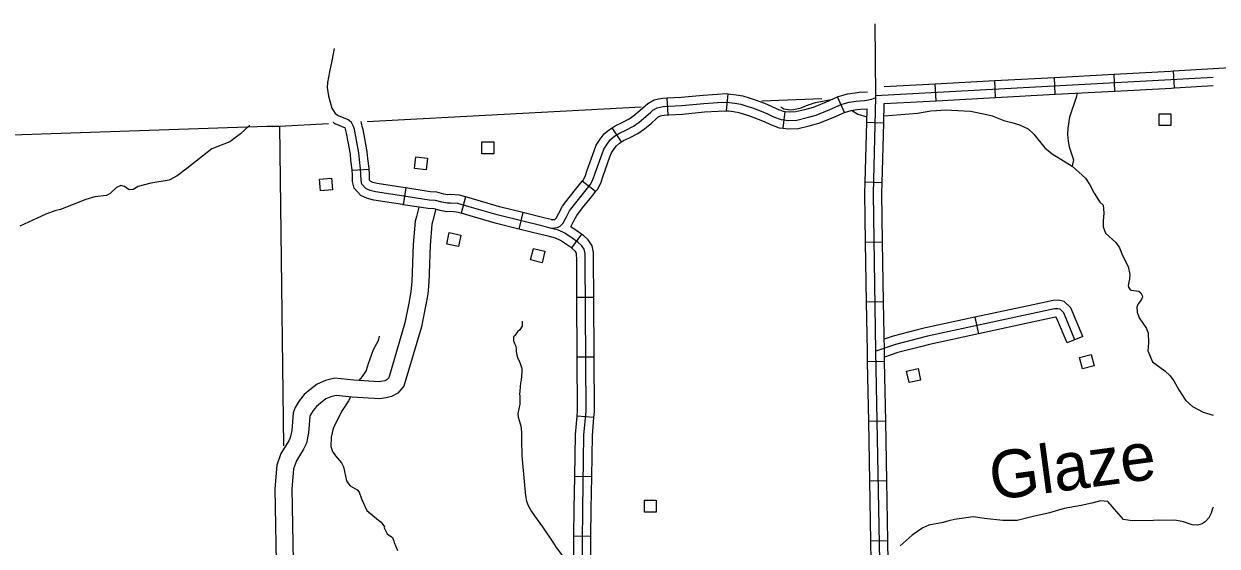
# Model space of a CAD drawing. Extents: x 1369885 to 1370219, y 379980 to 380218.
# Drawn here: x 1370079.7 to 1370121.66, y 380108.07 to 380126.43 of the extents above; entities that cross this region are included whole.
import ezdxf

# ---------------------------------------------------------------- set-up
doc = ezdxf.new("R2010")
doc.units = 0
for name, color, linetype in [('Level 1', 7, 'Continuous'), ('Level 30', 7, 'Continuous'), ('Level 32', 7, 'Continuous'), ('Level 35', 7, 'Continuous'), ('Level 45', 7, 'Continuous'), ('Level 46', 7, 'Continuous'), ('Level 5', 7, 'Continuous'), ('Level 56', 7, 'Continuous')]:
    doc.layers.add(name, color=color, linetype=linetype)

msp = doc.modelspace()

# ---------------------------------------------------------------- linework, layer by layer
at = {"layer": 'Level 1'}
for points in [[(1370091.768, 380123.003), (1370101.408, 380123.518)], [(1370105.652, 380123.724), (1370107.758, 380123.802)], [(1370068.595, 380122.2), (1370071.687, 380122.275), (1370088.242, 380122.837), (1370088.683, 380122.838), (1370090.411, 380122.931)]]:
    msp.add_lwpolyline(points, dxfattribs=at)
at = {"layer": 'Level 30'}
msp.add_lwpolyline([(1370121.526, 380124.859), (1370128.518, 380125.268)], dxfattribs=at)
at = {"layer": 'Level 32'}
for p, q in [((1370120.169, 380124.182), (1370120.135, 380124.777)), ((1370111.779, 380123.728), (1370111.747, 380124.324)), ((1370113.876, 380123.841), (1370113.844, 380124.437)), ((1370115.974, 380123.955), (1370115.942, 380124.55)), ((1370118.071, 380124.068), (1370118.039, 380124.664)), ((1370104.413, 380123.376), (1370104.465, 380123.97)), ((1370108.556, 380123.317), (1370108.313, 380123.862)), ((1370102.362, 380123.232), (1370102.327, 380123.828)), ((1370106.397, 380122.76), (1370106.469, 380123.352)), ((1370100.714, 380122.279), (1370100.383, 380122.775)), ((1370109.94, 380122.944), (1370109.343, 380122.96)), ((1370091.84, 380121.31), (1370091.244, 380121.275)), ((1370099.808, 380120.533), (1370099.336, 380120.898)), ((1370093.13, 380120.662), (1370093.037, 380120.073)), ((1370109.886, 380120.845), (1370109.289, 380120.86)), ((1370095.234, 380120.344), (1370095.073, 380119.77)), ((1370097.252, 380119.795), (1370097.108, 380119.216)), ((1370099.307, 380119.034), (1370098.953, 380118.554)), ((1370109.9, 380118.757), (1370109.303, 380118.747)), ((1370099.745, 380116.813), (1370099.148, 380116.81)), ((1370109.935, 380116.657), (1370109.338, 380116.647)), ((1370099.757, 380114.713), (1370099.16, 380114.709)), ((1370109.97, 380114.558), (1370109.373, 380114.547)), ((1370099.749, 380112.585), (1370099.155, 380112.638)), ((1370110.009, 380112.458), (1370109.412, 380112.447)), ((1370099.671, 380110.509), (1370099.074, 380110.519)), ((1370110.047, 380110.358), (1370109.451, 380110.347)), ((1370099.643, 380108.411), (1370099.046, 380108.417)), ((1370110.086, 380108.258), (1370109.489, 380108.247))]:
    msp.add_line(p, q, dxfattribs=at)
for points in [[(1370109.666, 380123.913), (1370109.633, 380126.43)], [(1370090.608, 380125.566), (1370090.525, 380125.13), (1370090.448, 380124.744), (1370090.376, 380124.374), (1370090.36, 380124.187), (1370090.409, 380123.883), (1370090.531, 380123.465), (1370090.652, 380123.276), (1370090.773, 380123.194), (1370091.099, 380123.062), (1370091.214, 380122.984)], [(1370118.039, 380124.664), (1370120.023, 380124.771), (1370120.135, 380124.777)], [(1370120.135, 380124.777), (1370121.526, 380124.859)], [(1370109.666, 380123.913), (1370120.04, 380124.473), (1370121.526, 380124.56)], [(1370109.96, 380124.228), (1370111.747, 380124.324)], [(1370111.747, 380124.324), (1370113.844, 380124.437)], [(1370113.844, 380124.437), (1370115.942, 380124.55)], [(1370115.942, 380124.55), (1370118.039, 380124.664)], [(1370120.169, 380124.182), (1370121.526, 380124.261)], [(1370102.327, 380123.828), (1370102.352, 380123.829), (1370102.82, 380123.854), (1370103.59, 380123.928), (1370104.087, 380123.959), (1370104.396, 380123.976), (1370104.465, 380123.97)], [(1370104.465, 380123.97), (1370104.549, 380123.963), (1370104.748, 380123.939), (1370104.98, 380123.896), (1370105.211, 380123.827), (1370105.418, 380123.758), (1370105.745, 380123.637), (1370105.982, 380123.535), (1370106.182, 380123.437), (1370106.403, 380123.36), (1370106.469, 380123.352)], [(1370106.469, 380123.352), (1370106.619, 380123.334), (1370106.843, 380123.343), (1370107.168, 380123.424), (1370107.467, 380123.501), (1370107.928, 380123.691), (1370108.313, 380123.862)], [(1370106.886, 380123.046), (1370107.242, 380123.135), (1370107.561, 380123.218), (1370108.045, 380123.416), (1370108.442, 380123.593), (1370108.595, 380123.639), (1370108.728, 380123.68), (1370108.968, 380123.712), (1370109.106, 380123.728), (1370109.268, 380123.74), (1370109.343, 380123.752), (1370109.515, 380123.778), (1370109.585, 380123.81), (1370109.664, 380123.843)], [(1370108.313, 380123.862), (1370108.338, 380123.873), (1370108.508, 380123.924), (1370108.664, 380123.973), (1370108.931, 380124.008), (1370109.078, 380124.025), (1370109.366, 380124.046)], [(1370110.686, 380062.06), (1370110.698, 380062.13), (1370110.711, 380062.232), (1370110.72, 380062.336), (1370110.739, 380064.517), (1370110.44, 380079.332), (1370110.285, 380083.111), (1370110.263, 380085.837), (1370110.134, 380092.024), (1370109.791, 380107.409), (1370109.801, 380107.535), (1370109.665, 380114.927), (1370109.587, 380119.631), (1370109.578, 380120.463), (1370109.664, 380123.843), (1370109.666, 380123.913)], [(1370111.779, 380123.728), (1370113.876, 380123.841)], [(1370113.876, 380123.841), (1370115.974, 380123.955)], [(1370115.974, 380123.955), (1370118.071, 380124.068)], [(1370118.071, 380124.068), (1370120.057, 380124.175), (1370120.169, 380124.182)], [(1370098.207, 380119.249), (1370098.369, 380119.255), (1370098.466, 380119.269), (1370098.56, 380119.318), (1370098.656, 380119.409), (1370098.78, 380119.641), (1370098.89, 380119.856), (1370099.108, 380120.143), (1370099.381, 380120.48), (1370099.522, 380120.651), (1370099.615, 380120.772), (1370099.712, 380120.952), (1370099.787, 380121.185), (1370100.032, 380121.864), (1370100.097, 380122.025), (1370100.208, 380122.205), (1370100.321, 380122.354), (1370100.476, 380122.479), (1370100.641, 380122.589), (1370100.87, 380122.694), (1370101.139, 380122.834), (1370101.338, 380122.972), (1370101.572, 380123.17), (1370101.743, 380123.321), (1370101.821, 380123.391), (1370101.977, 380123.482)], [(1370100.383, 380122.775), (1370100.495, 380122.85), (1370100.739, 380122.962), (1370100.985, 380123.09), (1370101.156, 380123.209), (1370101.377, 380123.396), (1370101.544, 380123.543), (1370101.644, 380123.634), (1370101.868, 380123.763), (1370102.022, 380123.797), (1370102.153, 380123.817), (1370102.327, 380123.828)], [(1370101.977, 380123.482), (1370102.077, 380123.504), (1370102.184, 380123.52), (1370102.369, 380123.531), (1370102.842, 380123.556), (1370103.614, 380123.631), (1370104.104, 380123.661), (1370104.391, 380123.677), (1370104.518, 380123.666), (1370104.703, 380123.644), (1370104.909, 380123.606)], [(1370104.909, 380123.606), (1370105.121, 380123.542), (1370105.319, 380123.476), (1370105.634, 380123.36), (1370105.857, 380123.264), (1370106.067, 380123.161), (1370106.335, 380123.068), (1370106.607, 380123.035), (1370106.886, 380123.046)], [(1370108.547, 380123.313), (1370108.682, 380123.354), (1370108.792, 380123.388), (1370109.004, 380123.416), (1370109.134, 380123.43), (1370109.356, 380123.447)], [(1370109.343, 380122.96), (1370109.356, 380123.447)], [(1370109.94, 380122.944), (1370109.957, 380123.63)], [(1370109.957, 380123.63), (1370111.779, 380123.728)], [(1370100.714, 380122.279), (1370100.787, 380122.328), (1370101.001, 380122.426), (1370101.294, 380122.578), (1370101.52, 380122.735), (1370101.767, 380122.944), (1370101.942, 380123.099), (1370101.997, 380123.149), (1370102.087, 380123.2), (1370102.132, 380123.21), (1370102.216, 380123.223), (1370102.362, 380123.232)], [(1370102.362, 380123.232), (1370102.386, 380123.233), (1370102.864, 380123.258), (1370103.637, 380123.333), (1370104.122, 380123.363), (1370104.387, 380123.378), (1370104.413, 380123.376)], [(1370104.413, 380123.376), (1370104.487, 380123.37), (1370104.658, 380123.349), (1370104.839, 380123.315), (1370105.031, 380123.258), (1370105.221, 380123.194), (1370105.523, 380123.083), (1370105.732, 380122.992), (1370105.952, 380122.886), (1370106.267, 380122.775), (1370106.397, 380122.76)], [(1370106.397, 380122.76), (1370106.595, 380122.736), (1370106.929, 380122.749), (1370107.315, 380122.846), (1370107.656, 380122.934), (1370108.163, 380123.142), (1370108.556, 380123.317)], [(1370090.574, 380122.969), (1370090.632, 380122.93), (1370091.001, 380122.779)], [(1370091.244, 380121.275), (1370091.242, 380121.301), (1370091.201, 380121.632), (1370091.183, 380121.853), (1370091.101, 380122.288), (1370091.05, 380122.589), (1370091.036, 380122.639), (1370091.001, 380122.779)], [(1370099.331, 380107.04), (1370099.354, 380109.38), (1370099.396, 380111.973), (1370099.47, 380112.808), (1370099.438, 380118.145), (1370099.436, 380118.356), (1370099.408, 380118.507), (1370099.318, 380118.631), (1370099.185, 380118.753), (1370098.987, 380118.899), (1370098.719, 380119.07), (1370098.504, 380119.178), (1370098.207, 380119.249), (1370097.956, 380119.313), (1370096.348, 380119.713), (1370095.278, 380120.022), (1370094.964, 380120.11), (1370094.705, 380120.127), (1370094.594, 380120.121), (1370094.403, 380120.156), (1370094.177, 380120.217), (1370093.949, 380120.232), (1370093.063, 380120.371), (1370092.069, 380120.528), (1370091.876, 380120.574), (1370091.722, 380120.645), (1370091.584, 380120.791), (1370091.556, 380120.927), (1370091.551, 380121.142), (1370091.54, 380121.328), (1370091.498, 380121.663), (1370091.479, 380121.893), (1370091.394, 380122.341), (1370091.341, 380122.653), (1370091.325, 380122.714), (1370091.297, 380122.824), (1370091.214, 380122.984)], [(1370091.84, 380121.31), (1370091.837, 380121.355), (1370091.795, 380121.693), (1370091.775, 380121.934), (1370091.688, 380122.394), (1370091.633, 380122.718), (1370091.613, 380122.789), (1370091.563, 380122.992)], [(1370099.336, 380120.898), (1370099.364, 380120.935), (1370099.436, 380121.069), (1370099.505, 380121.281), (1370099.753, 380121.97), (1370099.83, 380122.16), (1370099.962, 380122.374), (1370100.106, 380122.564), (1370100.299, 380122.719), (1370100.383, 380122.775)], [(1370109.289, 380120.86), (1370109.343, 380122.96)], [(1370109.886, 380120.845), (1370109.94, 380122.944)], [(1370099.808, 380120.533), (1370099.867, 380120.609), (1370099.988, 380120.834), (1370100.069, 380121.089), (1370100.31, 380121.757), (1370100.364, 380121.89), (1370100.455, 380122.037), (1370100.537, 380122.145), (1370100.652, 380122.238), (1370100.714, 380122.279)], [(1370093.037, 380120.073), (1370093.016, 380120.076), (1370092.011, 380120.235), (1370091.778, 380120.29), (1370091.544, 380120.399), (1370091.309, 380120.648), (1370091.259, 380120.892), (1370091.253, 380121.129), (1370091.244, 380121.275)], [(1370093.13, 380120.662), (1370093.109, 380120.666), (1370092.127, 380120.821), (1370091.974, 380120.857), (1370091.899, 380120.892), (1370091.859, 380120.934), (1370091.854, 380120.961), (1370091.849, 380121.155), (1370091.84, 380121.31)], [(1370098.239, 380119.549), (1370098.343, 380119.553), (1370098.372, 380119.557), (1370098.384, 380119.563), (1370098.416, 380119.593), (1370098.516, 380119.78), (1370098.637, 380120.016), (1370098.873, 380120.328), (1370099.15, 380120.669), (1370099.288, 380120.837), (1370099.336, 380120.898)], [(1370095.234, 380120.344), (1370095.014, 380120.406), (1370094.707, 380120.426), (1370094.614, 380120.421), (1370094.469, 380120.448), (1370094.226, 380120.513), (1370093.982, 380120.528), (1370093.13, 380120.662)], [(1370098.93, 380119.289), (1370099.044, 380119.503), (1370099.144, 380119.697), (1370099.343, 380119.959), (1370099.612, 380120.291), (1370099.755, 380120.465), (1370099.808, 380120.533)], [(1370109.303, 380118.747), (1370109.289, 380119.626), (1370109.279, 380120.465), (1370109.289, 380120.86)], [(1370109.9, 380118.757), (1370109.886, 380119.635), (1370109.876, 380120.461), (1370109.886, 380120.845)], [(1370095.073, 380119.77), (1370094.913, 380119.814), (1370094.703, 380119.828), (1370094.575, 380119.822), (1370094.338, 380119.865), (1370094.129, 380119.921), (1370093.917, 380119.935), (1370093.037, 380120.073)], [(1370097.252, 380119.795), (1370096.425, 380120.001), (1370095.36, 380120.309), (1370095.234, 380120.344)], [(1370097.108, 380119.216), (1370096.27, 380119.425), (1370095.196, 380119.735), (1370095.073, 380119.77)], [(1370098.239, 380119.549), (1370098.028, 380119.602), (1370097.252, 380119.795)], [(1370099.307, 380119.034), (1370099.156, 380119.145), (1370098.93, 380119.289)], [(1370098.953, 380118.554), (1370098.818, 380118.653), (1370098.572, 380118.81), (1370098.401, 380118.896), (1370098.135, 380118.96), (1370097.883, 380119.024), (1370097.108, 380119.216)], [(1370099.745, 380116.813), (1370099.737, 380118.148), (1370099.734, 380118.386), (1370099.688, 380118.627), (1370099.542, 380118.831), (1370099.375, 380118.984), (1370099.307, 380119.034)], [(1370099.148, 380116.81), (1370099.14, 380118.142), (1370099.138, 380118.327), (1370099.127, 380118.386), (1370099.094, 380118.432), (1370098.996, 380118.522), (1370098.953, 380118.554)], [(1370109.338, 380116.647), (1370109.303, 380118.747)], [(1370109.935, 380116.657), (1370109.9, 380118.757)], [(1370099.16, 380114.709), (1370099.148, 380116.81)], [(1370099.757, 380114.713), (1370099.745, 380116.813)], [(1370109.373, 380114.547), (1370109.366, 380114.921), (1370109.338, 380116.647)], [(1370109.97, 380114.558), (1370109.963, 380114.932), (1370109.935, 380116.657)], [(1370099.155, 380112.638), (1370099.171, 380112.821), (1370099.16, 380114.709)], [(1370099.749, 380112.585), (1370099.768, 380112.796), (1370099.757, 380114.713)], [(1370109.412, 380112.447), (1370109.373, 380114.547)], [(1370110.009, 380112.458), (1370109.97, 380114.558)], [(1370099.074, 380110.519), (1370099.097, 380111.989), (1370099.155, 380112.638)], [(1370099.671, 380110.509), (1370099.694, 380111.958), (1370099.749, 380112.585)], [(1370109.451, 380110.347), (1370109.412, 380112.447)], [(1370110.047, 380110.358), (1370110.009, 380112.458)], [(1370099.046, 380108.417), (1370099.056, 380109.384), (1370099.074, 380110.519)], [(1370099.643, 380108.411), (1370099.653, 380109.376), (1370099.671, 380110.509)], [(1370109.489, 380108.247), (1370109.451, 380110.347)], [(1370110.086, 380108.258), (1370110.047, 380110.358)], [(1370099.037, 380106.312), (1370099.033, 380107.041), (1370099.046, 380108.417)], [(1370099.634, 380106.315), (1370099.629, 380107.04), (1370099.643, 380108.411)], [(1370109.521, 380106.146), (1370109.493, 380107.417), (1370109.502, 380107.544), (1370109.489, 380108.247)], [(1370110.117, 380106.16), (1370110.09, 380107.401), (1370110.099, 380107.526), (1370110.086, 380108.258)]]:
    msp.add_lwpolyline(points, dxfattribs=at)
at = {"layer": 'Level 35'}
for points in [[(1370116.746, 380123.996), (1370116.709, 380123.837), (1370116.476, 380123.152), (1370116.417, 380122.765), (1370116.407, 380122.537), (1370116.425, 380122.302), (1370116.465, 380122.112), (1370116.616, 380121.655), (1370116.57, 380121.421)], [(1370106.32, 380123.517), (1370106.431, 380123.445), (1370106.671, 380123.412), (1370106.782, 380123.417), (1370107.034, 380123.475), (1370107.222, 380123.563), (1370107.536, 380123.665), (1370108.144, 380123.779)], [(1370108.805, 380123.39), (1370109.023, 380123.25), (1370109.348, 380123.163)], [(1370109.956, 380123.198), (1370111.128, 380123.291), (1370111.599, 380123.369), (1370111.794, 380123.385), (1370112.095, 380123.411), (1370112.987, 380123.359), (1370113.508, 380123.252), (1370113.757, 380123.2), (1370114.159, 380123.037), (1370114.442, 380122.96), (1370114.716, 380122.884), (1370115.017, 380122.745), (1370115.216, 380122.55), (1370115.607, 380122.067), (1370115.859, 380121.866), (1370116.57, 380121.421), (1370117.03, 380121.005), (1370117.191, 380120.768), (1370117.335, 380120.475), (1370117.544, 380120.164), (1370117.652, 380120.053), (1370117.675, 380119.786), (1370117.652, 380119.497), (1370117.657, 380119.293), (1370117.738, 380119.077), (1370118.098, 380118.741), (1370118.234, 380118.555), (1370118.341, 380118.288), (1370118.541, 380117.897), (1370118.6, 380117.623), (1370118.587, 380117.471), (1370118.533, 380117.237), (1370118.552, 380117.177), (1370118.591, 380117.107), (1370118.644, 380117.07), (1370118.916, 380117.033), (1370118.982, 380116.976), (1370119.034, 380116.883), (1370119.036, 380116.835), (1370119, 380116.741), (1370118.887, 380116.592), (1370118.845, 380116.471), (1370118.857, 380116.291), (1370118.925, 380116.094), (1370119.176, 380115.721), (1370119.235, 380115.556), (1370119.249, 380115.221), (1370119.222, 380114.936), (1370119.393, 380114.552), (1370119.821, 380114.226), (1370120.012, 380114.055), (1370120.143, 380113.88), (1370120.315, 380113.568), (1370120.558, 380113.203), (1370120.798, 380112.981), (1370121.173, 380112.778), (1370121.526, 380112.669)], [(1370087.642, 380122.872), (1370087.316, 380122.568), (1370086.943, 380122.278), (1370086.311, 380122.032), (1370085.434, 380121.339), (1370085.085, 380121.085), (1370084.803, 380120.937), (1370084.159, 380120.83), (1370083.718, 380120.709), (1370083.538, 380120.612), (1370083.407, 380120.6), (1370083.233, 380120.71), (1370083.109, 380120.742), (1370082.956, 380120.678), (1370082.736, 380120.46), (1370082.599, 380120.4), (1370082.191, 380120.352), (1370081.88, 380120.259), (1370080.981, 380119.901), (1370080.788, 380119.851), (1370080.47, 380119.734), (1370079.553, 380119.323)], [(1370097.219, 380115.975), (1370097.219, 380115.802), (1370097.14, 380115.677), (1370097.058, 380115.607), (1370096.964, 380115.476), (1370096.924, 380115.431), (1370096.918, 380115.303), (1370096.951, 380115.193), (1370096.997, 380115.094), (1370097.018, 380115.002), (1370097.018, 380114.905), (1370097.037, 380114.797), (1370097.061, 380114.687), (1370097.122, 380114.584), (1370097.152, 380114.493), (1370097.21, 380114.31), (1370097.207, 380114.207), (1370097.184, 380113.903), (1370097.164, 380113.805), (1370097.155, 380113.671), (1370097.137, 380113.504), (1370097.131, 380113.428), (1370097.138, 380113.34), (1370097.141, 380113.255), (1370097.143, 380113.054), (1370097.073, 380112.728), (1370097.081, 380112.6), (1370097.16, 380112.336), (1370097.183, 380112.217), (1370097.194, 380112.022), (1370097.201, 380111.803), (1370097.209, 380111.237), (1370097.316, 380110.08)], [(1370092.189, 380115.451), (1370092.161, 380115.28), (1370091.979, 380114.971), (1370091.808, 380114.474), (1370091.731, 380114.248), (1370091.599, 380114.028), (1370091.483, 380113.888)], [(1370091.182, 380113.31), (1370091.117, 380113.177), (1370090.874, 380112.803), (1370090.574, 380112.2), (1370090.504, 380111.902), (1370090.494, 380111.571), (1370090.555, 380111.398), (1370090.655, 380111.245), (1370090.865, 380110.997), (1370090.941, 380110.851), (1370091.051, 380110.364), (1370091.118, 380110.255), (1370091.175, 380110.193), (1370091.422, 380110.049), (1370091.492, 380109.963), (1370091.571, 380109.734), (1370091.674, 380109.5), (1370091.763, 380109.315), (1370091.897, 380109.205), (1370092.17, 380108.979), (1370092.263, 380108.906), (1370092.382, 380108.747), (1370092.368, 380108.714), (1370092.481, 380108.498), (1370092.658, 380108.371), (1370092.714, 380108.248), (1370092.723, 380108.193), (1370092.84, 380107.913)], [(1370097.316, 380110.08), (1370097.339, 380109.834), (1370097.381, 380109.652), (1370097.433, 380109.498), (1370097.551, 380109.282), (1370097.659, 380109.13), (1370097.935, 380108.745), (1370098.304, 380108.205), (1370098.42, 380108.017), (1370098.602, 380107.769), (1370098.762, 380107.636), (1370099.036, 380107.416)], [(1370121.526, 380109.434), (1370121.502, 380109.386), (1370121.457, 380109.232), (1370121.369, 380109.065), (1370121.24, 380108.919), (1370121.143, 380108.851), (1370120.974, 380108.808), (1370120.791, 380108.82), (1370120.484, 380108.919), (1370120.175, 380108.981), (1370118.68, 380108.953), (1370118.37, 380109.008), (1370117.818, 380109.637), (1370117.566, 380109.666), (1370117.26, 380109.575), (1370116.886, 380109.502), (1370116.281, 380109.385), (1370115.765, 380109.24), (1370115.199, 380109.106), (1370114.63, 380108.969), (1370114.129, 380108.969), (1370113.487, 380109.044), (1370113.09, 380109.103), (1370112.43, 380109.002), (1370112.234, 380108.96), (1370112.034, 380108.895), (1370111.531, 380108.804), (1370111.313, 380108.706), (1370110.945, 380108.451), (1370110.512, 380108.083)]]:
    msp.add_lwpolyline(points, dxfattribs=at)
at = {"layer": 'Level 45'}
for p, q in [((1370113.145, 380116.114), (1370113.27, 380115.53)), ((1370116.937, 380115.439), (1370116.386, 380115.21))]:
    msp.add_line(p, q, dxfattribs=at)
for points in [[(1370116.937, 380115.439), (1370116.521, 380116.441), (1370116.287, 380116.666), (1370116.087, 380116.714), (1370115.903, 380116.707), (1370115.198, 380116.555)], [(1370116.662, 380115.324), (1370116.269, 380116.269), (1370116.139, 380116.395), (1370116.058, 380116.414), (1370115.94, 380116.41), (1370111.475, 380115.45), (1370110.352, 380115.159), (1370109.665, 380114.927)], [(1370115.198, 380116.555), (1370113.145, 380116.114)], [(1370113.145, 380116.114), (1370111.407, 380115.74), (1370111.082, 380115.656)], [(1370115.323, 380115.972), (1370113.27, 380115.53)], [(1370116.386, 380115.21), (1370116.018, 380116.097), (1370116.001, 380116.113), (1370115.978, 380116.112), (1370115.323, 380115.972)], [(1370111.082, 380115.656), (1370110.267, 380115.445), (1370109.956, 380115.34)], [(1370113.27, 380115.53), (1370111.544, 380115.159), (1370111.232, 380115.079)], [(1370111.232, 380115.079), (1370110.437, 380114.873), (1370109.967, 380114.714)]]:
    msp.add_lwpolyline(points, dxfattribs=at)
at = {"layer": 'Level 46'}
for points in [[(1370093.589, 380119.986), (1370093.51, 380119.662), (1370093.46, 380119.495), (1370093.389, 380118.674), (1370093.347, 380117.374), (1370093.31, 380117.004), (1370093.239, 380116.614), (1370093.101, 380115.92), (1370092.529, 380113.984), (1370092.476, 380113.922), (1370092.407, 380113.885), (1370092.321, 380113.863), (1370092.186, 380113.844), (1370091.299, 380113.9), (1370090.634, 380113.971), (1370090.305, 380113.886), (1370090.019, 380113.763), (1370089.751, 380113.559), (1370089.561, 380113.394), (1370089.381, 380113.182), (1370089.239, 380112.946), (1370089.164, 380112.759), (1370089.121, 380112.13), (1370089.067, 380111.878), (1370089.015, 380111.77), (1370088.74, 380111.328), (1370088.597, 380110.911), (1370088.525, 380110.088), (1370088.586, 380106.87)], [(1370094.181, 380119.894), (1370094.086, 380119.506), (1370094.049, 380119.383), (1370093.985, 380118.638), (1370093.942, 380117.335), (1370093.902, 380116.921), (1370093.825, 380116.503), (1370093.681, 380115.777), (1370093.064, 380113.691), (1370092.856, 380113.45), (1370092.628, 380113.326), (1370092.438, 380113.277), (1370092.209, 380113.245), (1370091.248, 380113.305), (1370090.679, 380113.366), (1370090.499, 380113.32), (1370090.322, 380113.244), (1370090.127, 380113.095), (1370089.986, 380112.973), (1370089.867, 380112.833), (1370089.775, 380112.68), (1370089.753, 380112.625), (1370089.714, 380112.047), (1370089.636, 380111.682), (1370089.538, 380111.482), (1370089.283, 380111.071), (1370089.185, 380110.786), (1370089.122, 380110.067), (1370089.182, 380106.918)]]:
    msp.add_lwpolyline(points, dxfattribs=at)
at = {"layer": 'Level 5'}
msp.add_lwpolyline([(1370088.683, 380122.838), (1370088.828, 380111.595)], dxfattribs=at)
at = {"layer": 'Level 56'}
for points in [[(1370119.625, 380122.858), (1370119.625, 380123.272), (1370120.04, 380123.272), (1370120.04, 380122.858)], [(1370095.806, 380121.866), (1370095.806, 380122.28), (1370096.221, 380122.28), (1370096.221, 380121.866)], [(1370093.437, 380121.339), (1370093.481, 380121.75), (1370093.894, 380121.707), (1370093.85, 380121.295)], [(1370090.133, 380120.559), (1370090.099, 380120.972), (1370090.513, 380121.006), (1370090.547, 380120.593)], [(1370094.573, 380118.685), (1370094.657, 380119.09), (1370095.064, 380119.005), (1370094.979, 380118.6)], [(1370097.519, 380118.129), (1370097.618, 380118.532), (1370098.021, 380118.433), (1370097.923, 380118.031)], [(1370116.935, 380114.296), (1370116.828, 380114.696), (1370117.23, 380114.803), (1370117.336, 380114.403)], [(1370110.832, 380113.819), (1370110.743, 380114.224), (1370111.149, 380114.313), (1370111.238, 380113.908)], [(1370101.52, 380109.265), (1370101.52, 380109.679), (1370101.935, 380109.679), (1370101.935, 380109.265)]]:
    msp.add_lwpolyline(points, close=True, dxfattribs=at)

# ---------------------------------------------------------------- texts
at = {"layer": 'Level 35'}
msp.add_text('Glaze', height=1.6802, rotation=7.5435, dxfattribs=at).set_placement((1370113.768, 380109.678))

doc.saveas('drawing.dxf')
